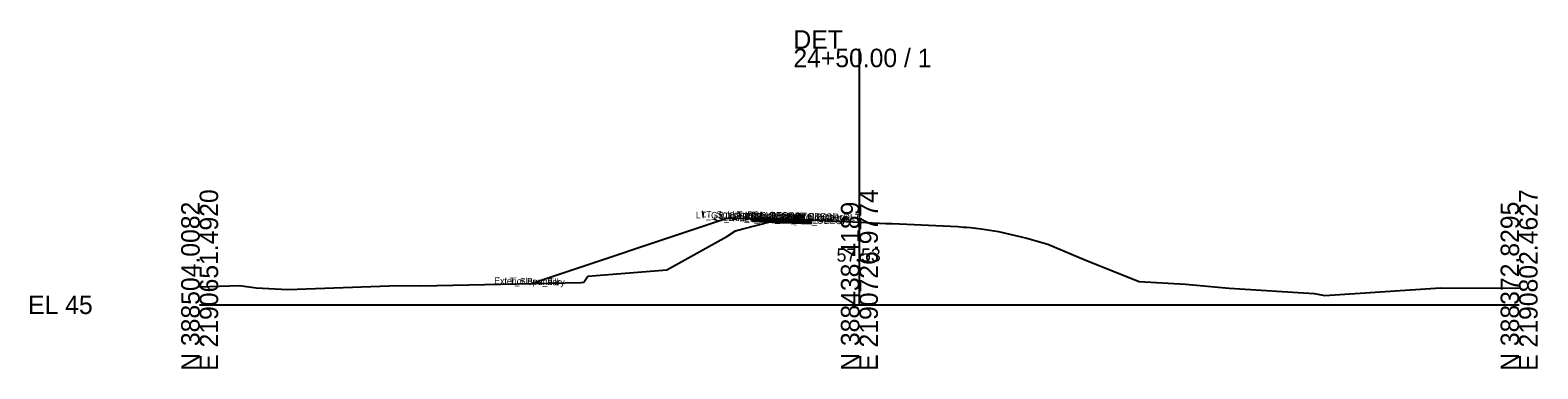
# Model space of a CAD drawing. Extents: x -26 to 1203, y -10 to 9543.
# Drawn here: x 974.3 to 1202.8, y 4490.3 to 4541.6 of the extents above; entities that cross this region are included whole.
import ezdxf

# ---------------------------------------------------------------- set-up
doc = ezdxf.new("R2010")
doc.units = 0
for name, color, linetype in [('Default', 7, 'Continuous'), ('Exist Cross Section Cell', 7, 'Continuous'), ('Exist XS Center Line Elevation Label', 7, 'Continuous'), ('Exist XS Ground Line', 7, 'Continuous'), ('Prop CMT Pvmt Course 1', 7, 'Continuous'), ('Prop CMT Pvmt Course 2', 7, 'Continuous'), ('Prop CMT Pvmt Surface', 7, 'Continuous'), ('Prop CMT Pvmt Surface Shoulder', 7, 'Continuous'), ('Prop CMT Shld Paved Course 1', 7, 'Continuous'), ('Prop CMT Shld Paved Course 2', 7, 'Continuous'), ('Prop CMT Slope Grass', 7, 'Continuous'), ('Prop CMT Subgrade Earthwork', 7, 'Continuous'), ('Scratch_Level_0', 7, 'Continuous')]:
    doc.layers.add(name, color=color, linetype=linetype)

msp = doc.modelspace()

# ---------------------------------------------------------------- linework, layer by layer
at = {"layer": 'Exist Cross Section Cell'}
for p, q in [((1100, 4500), (1100, 4538.77)), ((1000, 4500), (1100, 4500)), ((1100, 4500), (1200, 4500))]:
    msp.add_line(p, q, dxfattribs=at)
at = {"layer": 'Exist XS Ground Line'}
for p, q in [((1081.24, 4511.18), (1082.31, 4511.48)), ((1082.31, 4511.48), (1086.67, 4512.61)), ((1086.67, 4512.61), (1087.33, 4512.65)), ((1087.33, 4512.65), (1090.66, 4512.9)), ((1090.66, 4512.9), (1091.21, 4512.92)), ((1091.21, 4512.92), (1092.7, 4512.88)), ((1092.7, 4512.88), (1094.04, 4512.82)), ((1094.04, 4512.82), (1100, 4512.53)), ((1100, 4512.53), (1104.01, 4512.33)), ((1104.01, 4512.33), (1104.99, 4512.29)), ((1104.99, 4512.29), (1114.93, 4511.86)), ((1114.93, 4511.86), (1115.79, 4511.77)), ((1115.79, 4511.77), (1116.23, 4511.73)), ((1116.23, 4511.73), (1116.86, 4511.68)), ((1116.86, 4511.68), (1118.48, 4511.48)), ((1118.48, 4511.48), (1121.07, 4511.11)), ((1070.8, 4505.31), (1079.91, 4510.33)), ((1079.91, 4510.33), (1081.24, 4511.18)), ((1121.07, 4511.11), (1125.38, 4510.07)), ((1125.38, 4510.07), (1128.56, 4509.17)), ((1128.56, 4509.17), (1134.44, 4506.68)), ((1134.44, 4506.68), (1142.43, 4503.5)), ((1058.82, 4504.34), (1060.11, 4504.41)), ((1060.11, 4504.41), (1070.8, 4505.31)), ((1000, 4502.74), (1006.03, 4502.9)), ((1006.03, 4502.9), (1008.59, 4502.57)), ((1008.59, 4502.57), (1013.38, 4502.29)), ((1013.38, 4502.29), (1030.13, 4502.94)), ((1030.13, 4502.94), (1033.55, 4502.88)), ((1033.55, 4502.88), (1057.83, 4503.39)), ((1057.83, 4503.39), (1058.24, 4503.43)), ((1058.24, 4503.43), (1058.82, 4504.34)), ((1142.43, 4503.5), (1149.41, 4503.14)), ((1149.41, 4503.14), (1156.06, 4502.5)), ((1156.06, 4502.5), (1168.92, 4501.72)), ((1170.56, 4501.4), (1188.06, 4502.57)), ((1188.06, 4502.57), (1199.49, 4502.52)), ((1199.49, 4502.52), (1200, 4502.57)), ((1168.92, 4501.72), (1170.56, 4501.4))]:
    msp.add_line(p, q, dxfattribs=at)
at = {"layer": 'Prop CMT Pvmt Course 1'}
for points in [[(1092.7, 4512.79), (1086.78, 4513.03)], [(1086.78, 4513.03), (1086.78, 4512.78)], [(1086.78, 4512.78), (1092.7, 4512.54)], [(1092.7, 4512.54), (1092.7, 4512.79)]]:
    msp.add_lwpolyline(points, dxfattribs=at)
at = {"layer": 'Prop CMT Pvmt Course 2'}
for points in [[(1092.7, 4512.54), (1086.78, 4512.78)], [(1086.78, 4512.78), (1086.78, 4512.53)], [(1086.78, 4512.53), (1092.7, 4512.29)], [(1092.7, 4512.29), (1092.7, 4512.54)]]:
    msp.add_lwpolyline(points, dxfattribs=at)
at = {"layer": 'Prop CMT Pvmt Surface'}
msp.add_lwpolyline([(1092.7, 4512.79), (1086.78, 4513.03)], dxfattribs=at)
at = {"layer": 'Prop CMT Pvmt Surface Shoulder'}
msp.add_lwpolyline([(1086.78, 4513.03), (1084.79, 4513.11)], dxfattribs=at)
at = {"layer": 'Prop CMT Shld Paved Course 1'}
for points in [[(1086.78, 4513.03), (1084.79, 4513.11), (1084.55, 4512.87)], [(1084.55, 4512.87), (1086.78, 4512.78)], [(1086.78, 4512.78), (1086.78, 4513.03)]]:
    msp.add_lwpolyline(points, dxfattribs=at)
at = {"layer": 'Prop CMT Shld Paved Course 2'}
for points in [[(1086.78, 4512.78), (1084.55, 4512.87), (1084.05, 4512.89), (1083.81, 4512.65)], [(1083.81, 4512.65), (1086.78, 4512.53)], [(1086.78, 4512.53), (1086.78, 4512.78)]]:
    msp.add_lwpolyline(points, dxfattribs=at)
at = {"layer": 'Prop CMT Slope Grass'}
for points in [[(1079.74, 4513.01), (1049.97, 4503.05)], [(1084.79, 4513.11), (1079.74, 4513.01)]]:
    msp.add_lwpolyline(points, dxfattribs=at)
at = {"layer": 'Prop CMT Subgrade Earthwork'}
for points in [[(1083.81, 4512.65), (1083.38, 4513.08)], [(1086.78, 4512.53), (1083.81, 4512.65)], [(1086.78, 4512.53), (1092.7, 4512.29), (1092.71, 4512.88)]]:
    msp.add_lwpolyline(points, dxfattribs=at)

# ---------------------------------------------------------------- texts
at = {"layer": 'Default'}
msp.add_text('-', height=0.0001, dxfattribs=at).set_placement((1000, 4500))
at = {"layer": 'Exist Cross Section Cell'}
for s, p in [('DET', (1090, 4538.77)), ('24+50.00 / 1', (1090, 4535.97)), ('EL 45', (974, 4498.6))]:
    msp.add_text(s, height=2.8, dxfattribs=at).set_placement(p)
for s, p in [('E 2190651.4920', (1002.8, 4490)), ('E 2190726.9774', (1102.8, 4490)), ('E 2190802.4627', (1202.8, 4490)), ('N 388504.0082', (1000, 4490)), ('N 388438.4189', (1100, 4490)), ('N 388372.8295', (1200, 4490))]:
    msp.add_text(s, height=2.8, rotation=90, dxfattribs=at).set_placement(p)
at = {"layer": 'Exist XS Center Line Elevation Label'}
msp.add_text('57.53', height=2, dxfattribs=at).set_placement((1096.54, 4506.53))
at = {"layer": 'Scratch_Level_0'}
for s, p in [('LT_GS_OS_CTL', (1075.2, 4513.1)), ('LT_Sub_Trench_Out_DLT', (1076.03, 4513.23)), ('LT_Sub_Trench_Out', (1077.92, 4512.76)), ('LT_PS2_Shelf_Out', (1078.71, 4512.99)), ('LT_PS2_OEOP', (1080.34, 4512.95)), ('LT_PS1_OEOP', (1080.7, 4513.19)), ('LT_PV2_OEOT', (1082.53, 4512.86)), ('LT_Sub_OEOT', (1082.55, 4512.61)), ('LT_PV1_OEOT', (1082.65, 4513.11)), ('LT_Sub_OEEOP_DLT', (1086.67, 4513)), ('Exterior Boundary', (1087.38, 4512.99)), ('LT_PV2_OEEOP', (1088.1, 4512.63)), ('PV1_PGL', (1090.17, 4512.84)), ('LT_Sub_OEEOP', (1088.12, 4512.38)), ('Exterior Boundary', (1044.63, 4503.15)), ('LT_Slope_Fill', (1046.21, 4503.12))]:
    msp.add_text(s, height=1, rotation=358.8836, dxfattribs=at).set_placement(p)

doc.saveas('drawing.dxf')
